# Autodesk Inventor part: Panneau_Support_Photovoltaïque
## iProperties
Created: 2009-02
Part Number: Panneau_Support_Photovoltaïque
Document SubType Name: Sheet Metal
Designer: Alex_Cyril
Author: Alex_Cyril
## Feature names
1. Extrusion1
2. Extrusion2
3. Perçage1 [Hole]
4. Plaque1
5. Pli1
6. Plaque2
7. Pli2
8. Couper1
9. Couper2
10. Couper3
11. Couper4
12. Couper5
